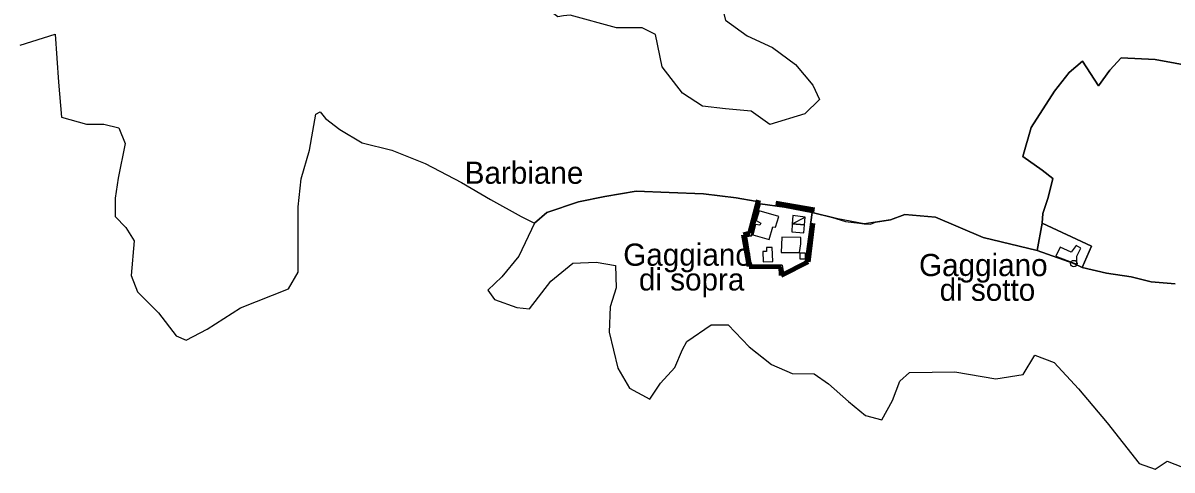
# Model space of a CAD drawing. Extents: x 645880 to 658994, y 884400 to 894744.
# Drawn here: x 654361 to 655242, y 890165 to 890509 of the extents above; entities that cross this region are included whole.
import ezdxf
from ezdxf.enums import TextEntityAlignment as Align

# ---------------------------------------------------------------- set-up
doc = ezdxf.new("R2010")
doc.units = 0
doc.header["$LTSCALE"] = 10
doc.header["$PDMODE"] = 32
doc.header["$PDSIZE"] = 5
doc.linetypes.add('MEDIUM_DASHED', pattern=[4.5, 3, -1.5])
for name, color, linetype, lineweight in [('1', 7, 'Continuous', 25), ('15', 7, 'MEDIUM_DASHED', 100), ('16', 7, 'Continuous', 25), ('18', 7, 'Continuous', 25), ('3', 7, 'Continuous', 25), ('6', 7, 'Continuous', 25)]:
    doc.layers.add(name, color=color, linetype=linetype, lineweight=lineweight)
doc.layers.add('60', color=7, linetype='Continuous')

msp = doc.modelspace()

# ---------------------------------------------------------------- linework, layer by layer
at = {"layer": '1'}
msp.add_line((654951.08, 890354.43), (654960.92, 890359.61), dxfattribs=at)
for points in [[(654926.43, 890369.77), (654919.88, 890345.22), (654916.07, 890344.79)], [(654966.42, 890363), (654945.05, 890367.23), (654926.43, 890369.77)], [(654916.07, 890344.79), (654919.14, 890325.39), (654920.09, 890322.99), (654943.36, 890322.78), (654944.42, 890316.43), (654961.34, 890325.74), (654966.42, 890363)]]:
    msp.add_lwpolyline(points, dxfattribs=at)
for points in [[(654925.8, 890364.27), (654923.4, 890356.93), (654926.86, 890354.96), (654926.27, 890353.29), (654922.97, 890353.99), (654920.81, 890345.95), (654933.42, 890342.25), (654936.1, 890352.19), (654938.32, 890351.76), (654940.82, 890360.04)], [(654951.08, 890354.43), (654950.76, 890348.18), (654960.07, 890347.55), (654960.5, 890353.58)], [(654951.4, 890360.67), (654951.08, 890354.43), (654960.5, 890353.58), (654960.92, 890359.61)], [(654943.06, 890344.15), (654942.49, 890332.52), (654956.55, 890332.46), (654957.71, 890338.95), (654957.63, 890344)], [(654931.3, 890336.11), (654931.37, 890333.16), (654928.62, 890333.15), (654928.78, 890325.19), (654936.06, 890325.4), (654935.67, 890336.31)]]:
    msp.add_lwpolyline(points, close=True, dxfattribs=at)
at = {"layer": '15'}
msp.add_lwpolyline([(654925.24, 890372.48), (654918.51, 890347.24), (654913.63, 890345.98), (654918.05, 890321.72), (654942.34, 890321.29), (654942.68, 890314.76), (654963.23, 890325.13), (654968.13, 890365.21)], close=True, dxfattribs=at)
at = {"layer": '16'}
msp.add_line((655167, 890323.87), (655138.98, 890333.95), dxfattribs=at)
for points in [[(655253.17, 890643.11), (655236.29, 890612.93), (655236.93, 890576.38), (655192.43, 890553.3), (655136.39, 890528.56), (655125, 890531.94), (655080.38, 890550.04), (655064.71, 890554.87), (655047.31, 890555.75), (655027.82, 890551.45), (655024.87, 890550.8), (655024.63, 890550.75), (655015.35, 890547.75), (654982.36, 890546.75), (654944.21, 890541.75), (654921.53, 890538.75), (654905.04, 890534.75), (654896.79, 890522.75), (654899.88, 890510.75), (654916.38, 890498.75), (654935.97, 890489.75), (654953.49, 890476.74), (654966.9, 890460.74), (654972.05, 890449.74)], [(654972.05, 890449.74), (654960.71, 890438.74), (654933.91, 890430.74), (654919.47, 890440.74), (654899.88, 890442.74), (654882.36, 890444.74), (654866.89, 890454.74), (654851.43, 890474.74), (654846.27, 890499.75), (654835.96, 890504.75), (654816.38, 890504.75), (654780.74, 890514.57), (654775.74, 890513.89), (654771.32, 890513.15), (654760.15, 890521.7), (654752.92, 890536.17), (654742.41, 890553.92), (654733.87, 890562.47), (654728.62, 890565.76), (654726.69, 890619.72), (654726.69, 890618.67), (654715.69, 890615.67), (654711.99, 890631.37), (654710.89, 890636.37)], [(654359.14, 890491.48), (654385.82, 890499.97), (654388.51, 890463.05), (654390.83, 890436.25), (654410.01, 890430.96), (654423.24, 890430.76), (654434.76, 890428.18), (654439.49, 890415.94), (654434.32, 890389.46), (654431.99, 890374.19), (654431.99, 890360.04), (654440.15, 890351.56), (654446.57, 890341.38), (654444.23, 890314.65), (654448.96, 890302.13), (654465.09, 890285.99), (654478.63, 890268.4), (654486.21, 890265.01), (654502.54, 890273.49), (654527.93, 890289.89)], [(655152.23, 890456.28), (655163.35, 890470.47), (655173.64, 890479.1), (655185.87, 890460.18), (655194.49, 890472.42), (655203.39, 890481.88), (655229.25, 890480.49), (655260.12, 890474.93), (655284.74, 890464.35), (655310.73, 890447.52)], [(655061.02, 890359.53), (655097.56, 890343.86), (655138.98, 890333.95), (655142.59, 890355), (655143.19, 890362.36), (655147.19, 890374.49), (655150.78, 890389.16), (655142.79, 890395.56), (655127.86, 890405.96), (655134.36, 890428.2), (655152.23, 890456.28)], [(654527.93, 890289.89), (654564.7, 890304.63), (654572.26, 890317.25), (654572.28, 890344.69), (654572.28, 890367.32), (654574.62, 890388.81), (654581.03, 890410.88), (654583.36, 890425.58), (654585.69, 890438.6), (654589.19, 890440.29), (654593.27, 890435.2), (654604.12, 890426.79), (654621.26, 890416.53), (654644, 890410.88), (654669.65, 890400.69), (654697.55, 890386.16), (654719.8, 890373.09), (654743.12, 890359.96), (654753.44, 890355)], [(654884.98, 890377.09), (654882.95, 890377.33), (654856.71, 890378.34), (654831.48, 890379.35), (654807.26, 890375.31), (654787.07, 890371.27), (654762.85, 890363.19), (654753.44, 890355), (654741.49, 890329.68), (654728.42, 890313.82), (654717.57, 890303.52), (654722.86, 890296.28), (654739.82, 890290.16), (654749.53, 890289.25), (654765.96, 890310.48), (654782.77, 890324.32), (654800.84, 890324.89), (654815.55, 890322.37), (654816.02, 890305.34), (654811.58, 890290.71), (654810.6, 890271.31), (654817.43, 890243.58), (654826.18, 890228.3), (654841.92, 890219.82), (654850.08, 890232.26), (654861.16, 890244.14), (654866.9, 890257.89), (654870.24, 890264.01), (654888.87, 890276.81), (654901.98, 890276.95), (654918.07, 890260.12), (654927.87, 890252.27), (654935.21, 890246.4)], [(654753.44, 890355), (654762.85, 890363.19), (654787.07, 890371.27), (654807.26, 890375.31), (654831.48, 890379.35), (654856.71, 890378.34), (654882.95, 890377.33), (654908.19, 890374.3), (654922.62, 890371.9)], [(654922.62, 890371.9), (654908.19, 890374.3), (654884.98, 890377.09)], [(654920.09, 890322.99), (654919.14, 890325.39), (654916.07, 890344.79), (654919.88, 890345.22), (654926.43, 890369.77), (654922.62, 890371.9)], [(654922.62, 890371.9), (654926.43, 890369.77), (654945.05, 890367.23), (654966.42, 890363), (654981.9, 890359.22)], [(654966.42, 890363), (654961.34, 890325.74), (654944.42, 890316.43), (654943.36, 890322.78), (654920.09, 890322.99)], [(655138.98, 890333.95), (655097.56, 890343.86), (655061.02, 890359.53), (655037.53, 890361.48), (655026.44, 890357.57), (655006.21, 890354.3), (654985.99, 890358.22), (654966.42, 890363)], [(655026.44, 890357.57), (655037.53, 890361.48), (655061.02, 890359.53)], [(654981.9, 890359.22), (654991.96, 890356.13), (655002.58, 890355.01)], [(655002.58, 890355.01), (655006.21, 890354.3), (655007.42, 890354.5)], [(655007.42, 890354.5), (655011.13, 890354.11), (655014.91, 890355.71), (655026.44, 890357.57)], [(655244.71, 890308.44), (655226.17, 890309.83), (655210.91, 890313.84), (655191.94, 890316.47), (655173.49, 890320.87), (655167, 890323.87)], [(654935.21, 890246.4), (654950.95, 890239.62), (654967.84, 890239.25), (654978.94, 890231.7), (654994.1, 890218.12)], [(654994.1, 890218.12), (655007.32, 890207.24), (655019.75, 890203.98), (655027.9, 890218.93), (655033.69, 890233.8), (655041.04, 890240.28), (655075.73, 890240.75), (655107.21, 890235.49), (655128.14, 890238.81), (655136.97, 890253.53), (655151.85, 890248.12), (655170.51, 890227.75), (655192.67, 890201.73), (655217.01, 890170.49), (655229.36, 890166.07), (655238.48, 890172.26), (655256.14, 890165.49)]]:
    msp.add_lwpolyline(points, dxfattribs=at)
msp.add_point((655167, 890323.87), dxfattribs=at)
at = {"layer": '18'}
for points in [[(654899.88, 890510.75), (654916.38, 890498.75), (654935.97, 890489.75), (654953.49, 890476.74), (654966.9, 890460.74), (654972.05, 890449.74), (654960.71, 890438.74), (654933.91, 890430.74), (654919.47, 890440.74), (654899.88, 890442.74), (654882.36, 890444.74), (654866.89, 890454.74), (654851.43, 890474.74), (654846.27, 890499.75), (654835.96, 890504.75), (654816.38, 890504.75), (654780.74, 890514.57)], [(654359.14, 890491.48), (654385.82, 890499.97), (654388.51, 890463.05), (654390.83, 890436.25), (654410.01, 890430.96), (654423.24, 890430.76), (654434.76, 890428.18), (654439.49, 890415.94), (654434.32, 890389.46), (654431.99, 890374.19), (654431.99, 890360.04), (654440.15, 890351.56), (654446.57, 890341.38), (654444.23, 890314.65), (654448.96, 890302.13), (654465.09, 890285.99), (654478.63, 890268.4), (654486.21, 890265.01), (654502.54, 890273.49), (654527.93, 890289.89)], [(655173.64, 890479.1), (655163.35, 890470.47), (655152.23, 890456.28), (655134.36, 890428.2), (655127.86, 890405.96), (655142.79, 890395.56), (655150.78, 890389.16), (655147.19, 890374.49), (655143.19, 890362.36)], [(655260.12, 890474.93), (655229.25, 890480.49), (655203.39, 890481.88), (655194.49, 890472.42), (655185.87, 890460.18), (655173.64, 890479.1)], [(654527.93, 890289.89), (654564.7, 890304.63), (654572.26, 890317.25), (654572.28, 890344.69), (654572.28, 890367.32), (654574.62, 890388.81), (654581.03, 890410.88), (654583.36, 890425.58), (654585.69, 890438.6), (654589.19, 890440.29), (654593.27, 890435.2), (654604.12, 890426.79), (654621.26, 890416.53), (654644, 890410.88), (654669.65, 890400.69), (654697.55, 890386.16), (654719.8, 890373.09), (654743.12, 890359.96), (654753.44, 890355), (654741.49, 890329.68), (654728.42, 890313.82), (654717.57, 890303.52), (654722.86, 890296.28), (654739.82, 890290.16), (654749.53, 890289.25), (654765.96, 890310.48), (654782.77, 890324.32), (654800.84, 890324.89), (654815.55, 890322.37), (654816.02, 890305.34), (654811.58, 890290.71), (654810.6, 890271.31), (654817.43, 890243.58), (654826.18, 890228.3), (654841.92, 890219.82), (654850.08, 890232.26), (654861.16, 890244.14), (654866.9, 890257.89), (654870.24, 890264.01), (654888.87, 890276.81)], [(655143.19, 890362.36), (655142.59, 890355), (655180.49, 890337.38), (655173.49, 890320.87), (655191.94, 890316.47)], [(655191.94, 890316.47), (655210.91, 890313.84), (655226.17, 890309.83), (655244.71, 890308.44)], [(654888.87, 890276.81), (654901.98, 890276.95), (654918.07, 890260.12), (654935.21, 890246.4), (654950.95, 890239.62), (654967.84, 890239.25), (654978.94, 890231.7), (654994.1, 890218.12)], [(654994.1, 890218.12), (655007.32, 890207.24), (655019.75, 890203.98), (655027.9, 890218.93), (655033.69, 890233.8), (655041.04, 890240.28), (655075.73, 890240.75), (655107.21, 890235.49), (655128.14, 890238.81), (655136.97, 890253.53), (655151.85, 890248.12), (655170.51, 890227.75), (655192.67, 890201.73), (655217.01, 890170.49), (655229.36, 890166.07), (655238.48, 890172.26), (655256.14, 890165.49)]]:
    msp.add_lwpolyline(points, dxfattribs=at)
at = {"layer": '3'}
for points in [[(655138.98, 890333.95), (655167, 890323.87), (655173.49, 890320.87), (655180.49, 890337.38), (655142.59, 890355)], [(655156.39, 890336.57), (655153.18, 890329.55), (655169.29, 890323.35), (655169.36, 890329.61), (655172.41, 890335.75), (655168.7, 890337.88), (655165.03, 890332.6)]]:
    msp.add_lwpolyline(points, close=True, dxfattribs=at)
at = {"layer": '6'}
msp.add_lwpolyline([(654957.23, 890332.25), (654960.98, 890332.25), (654960.98, 890327.25), (654957.23, 890327.25)], close=True, dxfattribs=at)

# ---------------------------------------------------------------- texts
at = {"layer": '60'}
for s, p in [('Barbiane', (654745.41, 890385.13)), ('Gaggiano ', (654873.93, 890322.24)), ('Gaggiano ', (655100.73, 890314.31)), ('di sopra', (654873.94, 890303.25)), ('di sotto', (655100.74, 890295.32))]:
    msp.add_text(s, height=17, dxfattribs=at).set_placement(p, align=Align.CENTER)

doc.saveas('drawing.dxf')
